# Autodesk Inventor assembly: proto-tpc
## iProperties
Shininess: 64.0
Length Units: 11272
Angle Units: 11279
Time Units: 11290
Mass Units: 11286
Length Display Precision: 3
Angle Display Precision: 2
Compacted: True
Part Number: proto-tpc
Document SubType Name: Assembly
Created: 2004-08
Designer: Lori
Manufacturer: Standard
Standards Organization: Custom
Density: 0.0
Volumn: 0.0
Area: 0.0
PropertySet Name: Model Information
Control State: 0
Master: False
Checked Out: False
Author: Lori
